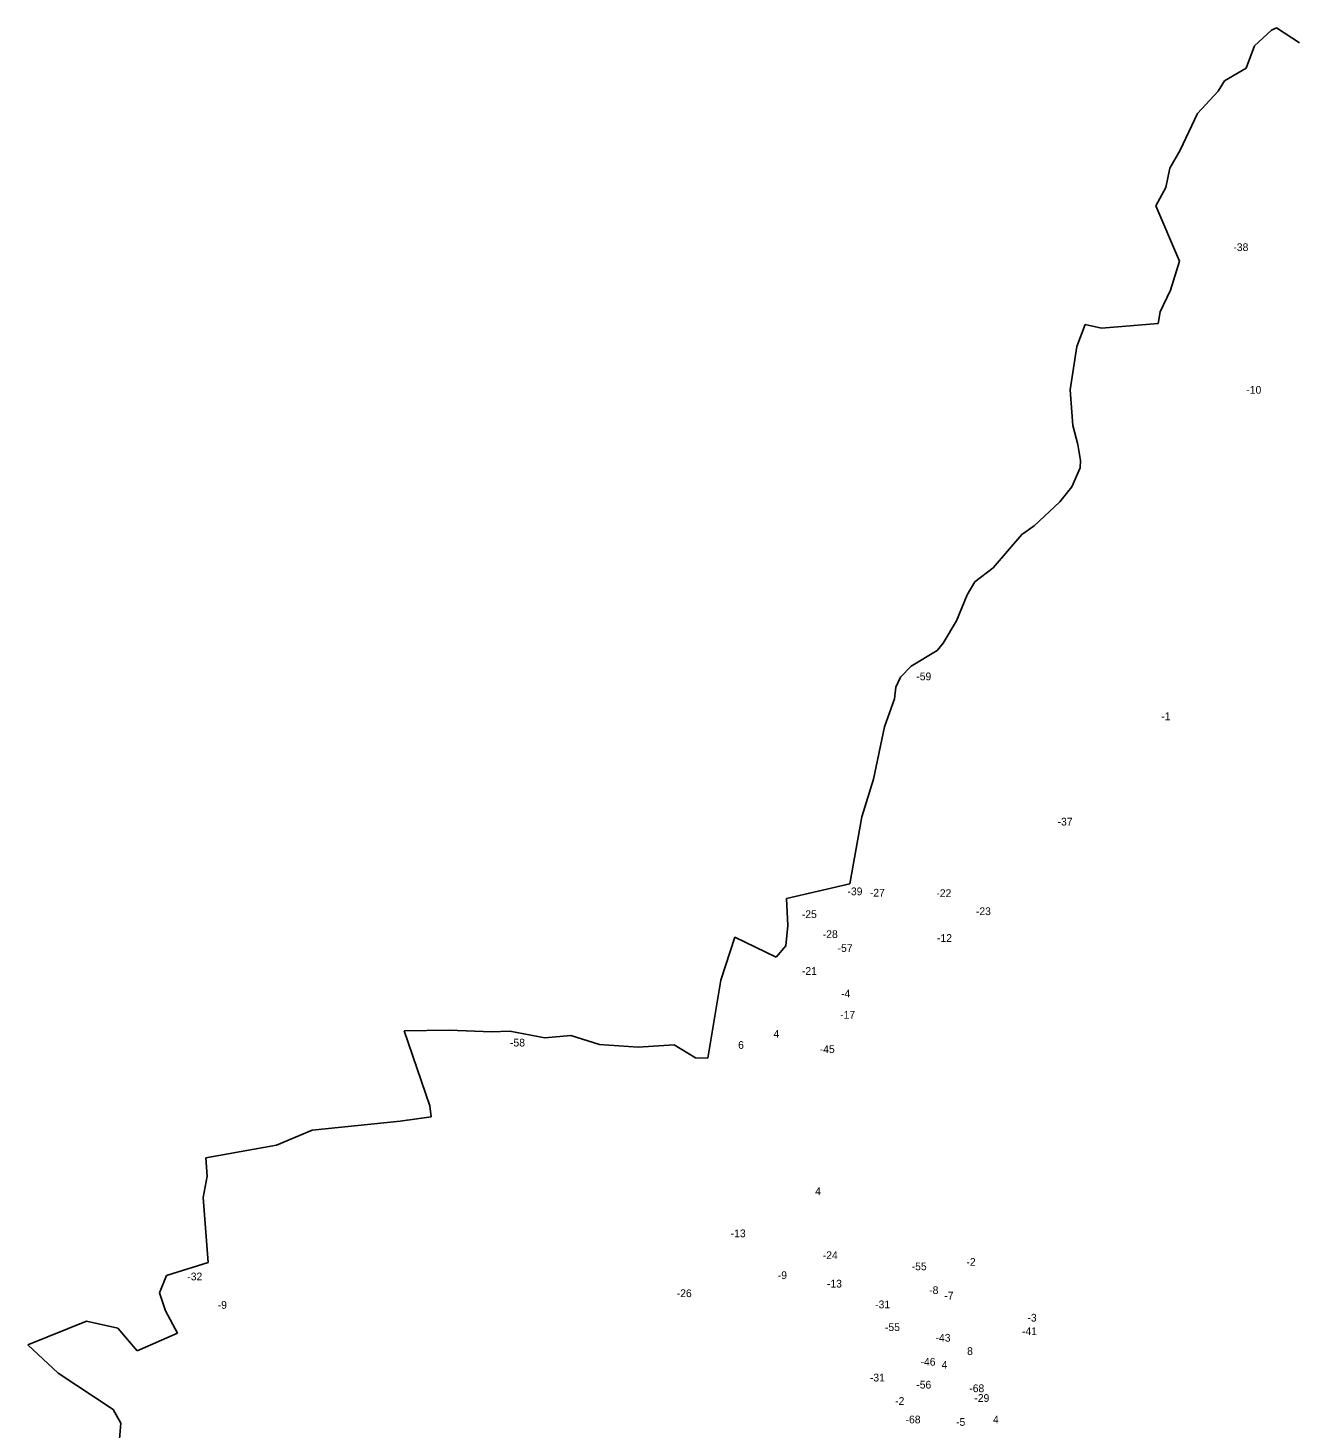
# Model space of a CAD drawing. Extents: x -790002 to -785628, y -971900 to -967971.
# Drawn here: x -789438 to -787802, y -969779 to -967971 of the extents above; entities that cross this region are included whole.
import ezdxf

# ---------------------------------------------------------------- set-up
doc = ezdxf.new("R2010")
doc.units = 0
doc.layers.add('Vrstva 13', color=7, linetype='Continuous')
doc.layers.add('Vrstva 15', color=7, linetype='Continuous')

msp = doc.modelspace()

# ---------------------------------------------------------------- linework, layer by layer
at = {"layer": 'Vrstva 13'}
for p, q in [((-787852.87, -967993.7), (-787830.84, -967973.57)), ((-787830.84, -967973.57), (-787824.45, -967970.7)), ((-787824.45, -967970.7), (-787794.43, -967989.87)), ((-787863.73, -968022.45), (-787852.87, -967993.7)), ((-787891.51, -968038.75), (-787863.73, -968022.45)), ((-787899.9, -968052.3), (-787891.51, -968038.75)), ((-787926.25, -968081.06), (-787899.9, -968052.3)), ((-787948.76, -968128.66), (-787926.25, -968081.06)), ((-787962.21, -968151.58), (-787948.76, -968128.66)), ((-787967.24, -968176.58), (-787962.21, -968151.58)), ((-787980.29, -968200.3), (-787967.24, -968176.58)), ((-787949.63, -968271.86), (-787980.29, -968200.3)), ((-787961.45, -968309.56), (-787949.63, -968271.86)), ((-787974.86, -968337.35), (-787961.45, -968309.56)), ((-787977.42, -968352.68), (-787974.86, -968337.35)), ((-788082.17, -968382.08), (-788071.63, -968353.96)), ((-788071.63, -968353.96), (-788050.55, -968358.43)), ((-788050.55, -968358.43), (-787977.42, -968352.68)), ((-788091.11, -968437.98), (-788082.17, -968382.08)), ((-788087.67, -968484.47), (-788091.11, -968437.98)), ((-788081.13, -968508.75), (-788087.67, -968484.47)), ((-788077.61, -968529.67), (-788081.13, -968508.75)), ((-788078.25, -968538.94), (-788077.61, -968529.67)), ((-788088.63, -968563.54), (-788078.25, -968538.94)), ((-788104.27, -968582.7), (-788088.63, -968563.54)), ((-788137.65, -968613.85), (-788104.27, -968582.7)), ((-788190.33, -968668.01), (-788153.61, -968624.88)), ((-788153.61, -968624.88), (-788137.65, -968613.85)), ((-788214.12, -968686.22), (-788190.33, -968668.01)), ((-788223.86, -968702.99), (-788214.12, -968686.22)), ((-788237.91, -968736.53), (-788223.86, -968702.99)), ((-788255, -968765.45), (-788237.91, -968736.53)), ((-788262.82, -968774.87), (-788255, -968765.45)), ((-788296.51, -968795.16), (-788262.82, -968774.87)), ((-788310.41, -968809.37), (-788296.51, -968795.16)), ((-788318.15, -968837.48), (-788316.23, -968822.14)), ((-788316.23, -968822.14), (-788310.41, -968809.37)), ((-788330.92, -968873.58), (-788318.15, -968837.48)), ((-788345.29, -968940.99), (-788330.92, -968873.58)), ((-788359.98, -968989.87), (-788345.29, -968940.99)), ((-788375.64, -969076.62), (-788359.98, -968989.87)), ((-788457.71, -969095.47), (-788375.64, -969076.62)), ((-788455.79, -969130.29), (-788457.71, -969095.47)), ((-788458.35, -969156.49), (-788455.79, -969130.29)), ((-788542.34, -969200.9), (-788524.45, -969145.31)), ((-788524.45, -969145.31), (-788470.8, -969171.18)), ((-788470.8, -969171.18), (-788458.35, -969156.49)), ((-788559.26, -969301.85), (-788542.34, -969200.9)), ((-788951.68, -969266.25), (-788893.39, -969265.28)), ((-788918.22, -969363.37), (-788951.68, -969266.25)), ((-788893.39, -969265.28), (-788838.78, -969267.52)), ((-788838.78, -969267.52), (-788814.83, -969266.56)), ((-788814.83, -969266.56), (-788769.81, -969275.51)), ((-788769.81, -969275.51), (-788736.27, -969272.31)), ((-788736.27, -969272.31), (-788699.23, -969284.13)), ((-788699.23, -969284.13), (-788649.09, -969287.65)), ((-788649.09, -969287.65), (-788602.78, -969284.45)), ((-788602.78, -969284.45), (-788575, -969301.38)), ((-788575, -969301.38), (-788559.26, -969301.85)), ((-788916.78, -969377.42), (-788918.22, -969363.37)), ((-789070.3, -969394.84), (-788956.86, -969383.01)), ((-788956.86, -969383.01), (-788916.78, -969377.42)), ((-789116.61, -969414.01), (-789070.3, -969394.84)), ((-789207.94, -969430.3), (-789116.61, -969414.01)), ((-789206.02, -969453.94), (-789207.94, -969430.3)), ((-789211.13, -969481.73), (-789206.02, -969453.94)), ((-789204.74, -969565.76), (-789211.13, -969481.73)), ((-789258.71, -969582.37), (-789204.74, -969565.76)), ((-789267.66, -969604.73), (-789258.71, -969582.37)), ((-789259.99, -969628.05), (-789267.66, -969604.73)), ((-789244.35, -969656.84), (-789259.99, -969628.05)), ((-789437.64, -969672.17), (-789361.87, -969641.5)), ((-789361.87, -969641.5), (-789321.63, -969650.45)), ((-789321.63, -969650.45), (-789296.72, -969679.84)), ((-789296.72, -969679.84), (-789244.35, -969656.84)), ((-789398.52, -969708.75), (-789437.64, -969672.17)), ((-789327.46, -969755.55), (-789398.52, -969708.75)), ((-789317.88, -969773.12), (-789327.46, -969755.55)), ((-789319.79, -969799), (-789317.88, -969773.12))]:
    msp.add_line(p, q, dxfattribs=at)

# ---------------------------------------------------------------- texts
at = {"layer": 'Vrstva 15'}
for s, p in [('-38', (-787880.03, -968258.83)), ('-10', (-787863.345, -968443.17)), ('-59', (-788289.764, -968813.39)), ('-1', (-787973.304, -968864.98)), ('-37', (-788107.179, -969001.06)), ('-39', (-788378.724, -969091.13)), ('-27', (-788349.809, -969092.92)), ('-22', (-788263.82, -969093.45)), ('-25', (-788437.67, -969120.63)), ('-23', (-788212.74, -969116.83)), ('-28', (-788410.62, -969146.46)), ('-12', (-788263.014, -969151.42)), ('-57', (-788391.469, -969164.41)), ('-21', (-788437.554, -969194.01)), ('-4', (-788387.016, -969223.17)), ('-17', (-788388.154, -969250.63)), ('-58', (-788814.78, -969286.55)), ('4', (-788474.242, -969275.15)), ('6', (-788520, -969289.56)), ('-45', (-788414.496, -969294.99)), ('4', (-788420.402, -969478.33)), ('-13', (-788529.664, -969533.01)), ('-24', (-788410.616, -969561.19)), ('-55', (-788295.72, -969575.66)), ('-2', (-788225.02, -969569.94)), ('-32', (-789231.76, -969588.67)), ('-9', (-788468.744, -969587.09)), ('-26', (-788599.334, -969610.38)), ('-13', (-788405.234, -969597.97)), ('-8', (-788273.1, -969606.38)), ('-7', (-788253.569, -969613.45)), ('-9', (-789192.474, -969625.42)), ('-31', (-788342.994, -969624.79)), ('-3', (-788146.21, -969641.98)), ('-55', (-788330.26, -969654.22)), ('-43', (-788264.926, -969667.9)), ('-41', (-788153.19, -969659.47)), ('8', (-788224.146, -969685.04)), ('-46', (-788284.3, -969698.9)), ('4', (-788256.992, -969702.73)), ('-31', (-788349.784, -969719.37)), ('-56', (-788289.774, -969728.52)), ('-68', (-788221.284, -969733.19)), ('-2', (-788317.12, -969749.58)), ('-29', (-788214.784, -969745.71)), ('-68', (-788303.664, -969773.44)), ('-5', (-788238.38, -969776.65)), ('4', (-788190.642, -969773.45))]:
    msp.add_text(s, height=10, dxfattribs=at).set_placement(p)

doc.saveas('drawing.dxf')
